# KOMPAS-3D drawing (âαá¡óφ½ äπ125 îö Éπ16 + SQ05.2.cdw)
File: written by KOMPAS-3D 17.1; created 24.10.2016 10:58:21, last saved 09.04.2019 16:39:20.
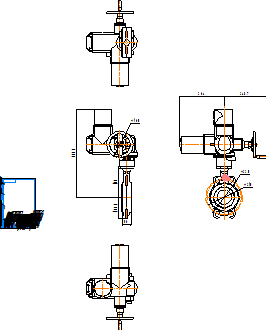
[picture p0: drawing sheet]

Sheet 1: A4, portrait

Title block, sheet 1: name: Гранвэл Ду125 МФ Ру16 + / SQ05.2; material: Внимание! Данный продукт является объектом авторского права ООО «Торговый Дом АДЛ». / Запрещается изменение, копирование, распространение / (в том числе путем копирования на другие сайты и ресурсы в Интернете) / или любое иное использование информации и объектов без предварительного / согласия правообладателя (ООО «Торговый Дом АДЛ»).; mass: 31,5; sheets: 1; organisation: ООО "Торговый дом АДЛ"; sheet format: A4; stored path: \\adlc.lan\data\АДЛ_ПКД\3D-модели\ADL production\Дисковые поворотные затворы ГРАНВЭЛ\межфланцевый с эл.приводом Auma Ру 16\KOMPAS 2D\Гранвэл Ду125 МФ Ру16 + SQ05.2.cdw

Views: Вид 1, Проекционный вид 3, Проекционный вид 4
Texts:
  Klimkovich
  ADL
Dimensions and other numbers on the sheet: 523,5; 160; 126,4; 180; 56; 1:1; 1; 31,5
